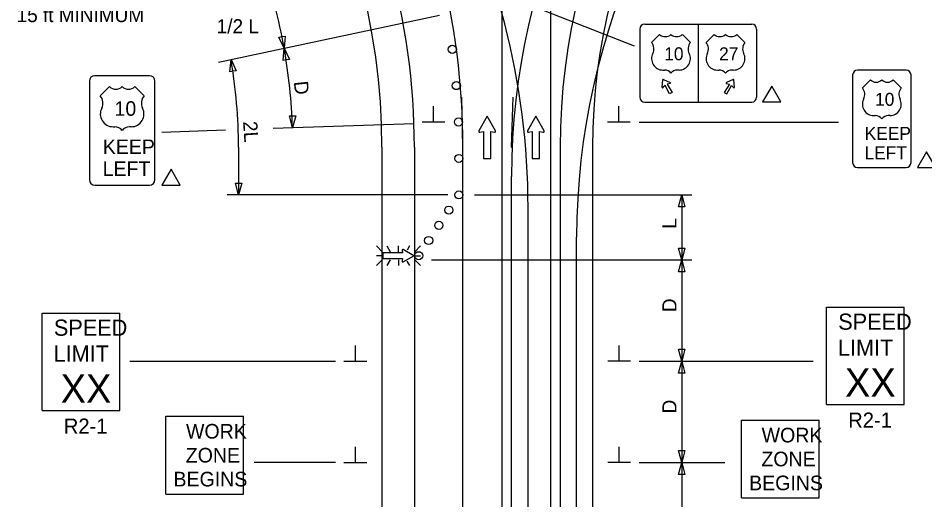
# Model space of a CAD drawing. Extents: x 16729 to 18500, y 5737 to 6974.
# Drawn here: x 16741.8 to 17189.6, y 6395.4 to 6633.2 of the extents above; entities that cross this region are included whole.
import ezdxf

# ---------------------------------------------------------------- set-up
doc = ezdxf.new("R2010")
doc.units = 0
for name, color, linetype in [('ALI_LEGAL_EX', 7, 'Continuous'), ('MT_SCRATCH_LEVEL_E', 7, 'Continuous'), ('PAVT_EDGE_EX', 7, 'Continuous'), ('TRAFFIC_SIGNS_PR', 7, 'Continuous'), ('TYPICAL_EX', 7, 'Continuous'), ('TYPICAL_TEXT_DIMEN_PR', 7, 'Continuous')]:
    doc.layers.add(name, color=color, linetype=linetype)

msp = doc.modelspace()

# ---------------------------------------------------------------- linework, layer by layer
at = {"layer": 'ALI_LEGAL_EX'}
for p, q in [((16980.68, 6974.12), (16980.68, 6155.98)), ((17004.68, 6974.12), (17004.68, 6155.98)), ((16980.68, 6891.53), (16980.68, 6027.61)), ((17004.68, 6891.53), (17004.68, 6027.61)), ((16961.51, 6069.17), (16961.51, 6569.52)), ((16985.51, 6054.68), (16985.51, 6555.03)), ((16993.65, 6039.29), (16993.65, 6539.64)), ((17017.65, 6024.8), (17017.65, 6525.15))]:
    msp.add_line(p, q, dxfattribs=at)
for points in [[(16961.46, 6569.17), (16961.51, 6569.52), (16960.94, 6594.16)], [(16985.56, 6569.17), (16985.51, 6569.52), (16986.34, 6594.15)], [(16961.51, 6469.17), (16961.51, 6494.17)], [(16985.51, 6469.17), (16985.51, 6494.17)]]:
    msp.add_lwpolyline(points, dxfattribs=at)
for centre, radius, start, end in [((16597.51, 6569.52), 364, 0, 57.2958), ((16629.65, 6539.64), 364, 0, 57.2958), ((17325.51, 6555.03), 340, 129.5666, 180), ((17357.65, 6525.15), 340, 129.5666, 180)]:
    msp.add_arc(centre, radius, start, end, dxfattribs=at)
at = {"layer": 'MT_SCRATCH_LEVEL_E'}
for p, q in [((16973.43, 6584.82), (16969.32, 6577.59)), ((16977.58, 6577.59), (16973.43, 6584.82)), ((16997.48, 6584.82), (16993.37, 6577.59)), ((17001.63, 6577.59), (16997.48, 6584.82)), ((16969.8, 6576.9), (16971.58, 6577.22)), ((16971.58, 6577.22), (16971.58, 6563.96)), ((16975.32, 6563.96), (16975.32, 6577.22)), ((16975.32, 6577.22), (16977.1, 6576.9)), ((16993.85, 6576.9), (16995.63, 6577.22)), ((16995.63, 6577.22), (16995.63, 6563.96)), ((16999.37, 6563.96), (16999.37, 6577.22)), ((16999.37, 6577.22), (17001.15, 6576.9)), ((16971.58, 6563.96), (16975.32, 6563.96)), ((16995.63, 6563.96), (16999.37, 6563.96))]:
    msp.add_line(p, q, dxfattribs=at)
for centre, start, end in [((16969.73, 6577.36), 150.4248, 279.9638), ((16977.17, 6577.36), 260.0362, 29.7731), ((16993.78, 6577.36), 150.4248, 279.9638), ((17001.22, 6577.36), 260.0362, 29.7731)]:
    msp.add_arc(centre, 0.463, start, end, dxfattribs=at)
at = {"layer": 'PAVT_EDGE_EX'}
for p, q in [((16921.51, 6569.52), (16921.51, 6043.9)), ((16937.51, 6569.52), (16937.51, 6043.9)), ((17009.51, 6569.52), (17009.51, 6043.9)), ((17025.51, 6569.52), (17025.51, 6043.9))]:
    msp.add_line(p, q, dxfattribs=at)
for centre, radius, start, end in [((16597.51, 6569.52), 340, 0, 62.1564), ((16597.51, 6569.52), 324, 0, 62.1564), ((17325.51, 6569.52), 316, 123.7854, 180), ((17325.51, 6569.52), 300, 123.7854, 180), ((17325.51, 6569.52), 300, 180, 180.00000277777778)]:
    msp.add_arc(centre, radius, start, end, dxfattribs=at)
at = {"layer": 'TRAFFIC_SIGNS_PR'}
for p, q in [((17048.86, 6627.84), (17048.86, 6594.19)), ((17051.26, 6630.24), (17104.13, 6630.24)), ((17077.7, 6630.24), (17077.7, 6591.79)), ((17106.53, 6627.84), (17106.53, 6594.19)), ((16806.71, 6604.81), (16779.71, 6604.81)), ((17153.94, 6605.16), (17153.94, 6561.91)), ((17180.37, 6607.57), (17156.34, 6607.57)), ((17182.77, 6561.91), (17182.77, 6605.16)), ((16777.01, 6602.11), (16777.01, 6553.51)), ((16809.41, 6553.51), (16809.41, 6602.11)), ((17059.85, 6599.15), (17060.14, 6602.78)), ((17060.51, 6602.99), (17063.79, 6601.42)), ((17094.88, 6602.99), (17091.6, 6601.42)), ((17095.54, 6599.15), (17095.25, 6602.78)), ((17051.26, 6591.79), (17104.13, 6591.79)), ((17156.34, 6559.51), (17180.37, 6559.51)), ((16779.71, 6550.81), (16806.71, 6550.81)), ((16921.58, 6517.92), (16918.76, 6520.74)), ((16923.88, 6520.74), (16925.51, 6517.92)), ((16929.67, 6517.92), (16929.67, 6520.74)), ((16935.13, 6520.74), (16933.93, 6518.65)), ((16940.57, 6520.74), (16937.75, 6517.92)), ((16921.58, 6515.89), (16918.76, 6515.89)), ((16937.75, 6515.89), (16940.57, 6515.89)), ((16921.58, 6513.86), (16918.76, 6511.04)), ((16925.53, 6513.86), (16923.9, 6511.04)), ((16929.67, 6513.86), (16929.67, 6511.04)), ((16933.85, 6513.23), (16935.11, 6511.04)), ((16940.57, 6511.04), (16937.75, 6513.86)), ((17141.06, 6490.51), (17179.46, 6490.51)), ((17141.06, 6442.51), (17141.06, 6490.51)), ((17179.46, 6442.51), (17179.46, 6490.51)), ((16753.73, 6487.55), (16792.13, 6487.55)), ((16753.73, 6439.55), (16753.73, 6487.55)), ((16792.13, 6439.55), (16792.13, 6487.55)), ((16753.73, 6439.55), (16792.13, 6439.55)), ((17141.06, 6442.51), (17179.46, 6442.51)), ((16814.75, 6398.28), (16814.75, 6436.68)), ((16814.75, 6436.68), (16853.15, 6436.68)), ((16853.15, 6398.28), (16853.15, 6436.68)), ((17099, 6396.4), (17099, 6434.8)), ((17099, 6434.8), (17137.4, 6434.8)), ((17137.4, 6396.4), (17137.4, 6434.8)), ((16814.75, 6398.28), (16853.15, 6398.28)), ((17099, 6396.4), (17137.4, 6396.4))]:
    msp.add_line(p, q, dxfattribs=at)
for points in [[(17063.75, 6600.94), (17062.34, 6600.55), (17064.86, 6596.56), (17063.53, 6595.8), (17061.33, 6599.97), (17060.29, 6598.94)], [(17091.64, 6600.94), (17093.05, 6600.55), (17090.53, 6596.56), (17091.86, 6595.8), (17094.06, 6599.97), (17095.1, 6598.94)], [(16931.49, 6518.57), (16931.72, 6517.28), (16922, 6517.28), (16922, 6514.53), (16931.72, 6514.53), (16931.49, 6513.23)], [(16931.99, 6512.88), (16937.3, 6515.89), (16931.99, 6518.93)]]:
    msp.add_lwpolyline(points, dxfattribs=at)
for centre in [(16956.26, 6617.81), (16958.22, 6599.92), (16959.28, 6581.96), (16959.5, 6563.96), (16959.5, 6545.96), (16959.5, 6545.96), (16954.53, 6538.45), (16949.56, 6530.94), (16944.59, 6523.44), (16939.62, 6515.93)]:
    msp.add_circle(centre, 2, dxfattribs=at)
for centre, radius, start, end in [((17051.26, 6627.84), 2.4, 90, 180), ((17051.26, 6627.84), 2.4, 90, 180), ((17104.13, 6627.84), 2.4, 0, 90), ((16779.71, 6602.1), 2.7, 90, 180), ((16806.71, 6602.1), 2.7, 0, 90), ((17156.34, 6605.16), 2.4, 90, 180), ((17180.37, 6605.16), 2.4, 0, 90), ((17060.4, 6602.76), 0.261, 64.4823, 175.5177), ((17063.68, 6601.19), 0.261, 285.9885, 64.4823), ((17091.71, 6601.19), 0.261, 115.5177, 254.0115), ((17094.99, 6602.76), 0.261, 4.4823, 115.5177), ((17060.11, 6599.13), 0.261, 175.5177, 314.0115), ((17095.28, 6599.13), 0.261, 225.9885, 4.4823), ((17051.26, 6594.19), 2.4, 180, 270), ((17104.13, 6594.19), 2.4, 270, 0), ((17156.34, 6561.91), 2.4, 180, 270), ((17180.37, 6561.91), 2.4, 270, 0), ((16779.71, 6553.5), 2.7, 180, 270), ((16806.71, 6553.5), 2.7, 270, 0), ((16931.83, 6518.63), 0.341, 61.4833, 189.9593), ((16931.83, 6513.18), 0.341, 170.7308, 298.8916)]:
    msp.add_arc(centre, radius, start, end, dxfattribs=at)
at = {"layer": 'TYPICAL_EX'}
for p, q in [((17054.62, 6621.23), (17058.62, 6625.23)), ((17073.84, 6621.23), (17069.84, 6625.23)), ((17081.55, 6621.23), (17085.55, 6625.23)), ((17100.77, 6621.23), (17096.77, 6625.23)), ((17060.22, 6607.6), (17061.02, 6607.6)), ((17068.24, 6607.6), (17067.44, 6607.6)), ((17087.15, 6607.6), (17087.95, 6607.6)), ((17095.17, 6607.6), (17094.37, 6607.6)), ((17158.74, 6598.76), (17162.75, 6602.76)), ((17177.97, 6598.76), (17173.96, 6602.76)), ((16782.41, 6594.91), (16786.91, 6599.41)), ((16804.01, 6594.91), (16799.51, 6599.41)), ((17164.34, 6585.13), (17165.14, 6585.13)), ((17172.36, 6585.13), (17171.56, 6585.13)), ((16788.7, 6579.59), (16789.6, 6579.59)), ((16797.71, 6579.59), (16796.81, 6579.59))]:
    msp.add_line(p, q, dxfattribs=at)
for centre, radius, start, end in [((17061.43, 6628.15), 4.05, 226.1404, 313.8596), ((17067.03, 6628.15), 4.05, 226.1404, 313.8596), ((17088.36, 6628.15), 4.05, 226.1404, 313.8596), ((17093.96, 6628.15), 4.05, 226.1404, 313.8596), ((17050.82, 6618.02), 4.97, 333.0977, 40.1936), ((17077.64, 6618.02), 4.97, 139.8064, 206.9023), ((17077.75, 6618.02), 4.97, 333.0977, 40.1936), ((17104.57, 6618.02), 4.97, 139.8064, 206.9023), ((17060.23, 6613.2), 5.6, 152.6698, 269.9013), ((17068.23, 6613.2), 5.6, 270.0987, 27.3302), ((17087.16, 6613.2), 5.6, 152.6698, 269.9013), ((17095.16, 6613.2), 5.6, 270.0987, 27.3302), ((17061.03, 6603.59), 4.01, 37.1038, 90.1385), ((17067.43, 6603.59), 4.01, 89.8615, 142.8962), ((17087.96, 6603.59), 4.01, 37.1038, 90.1385), ((17094.36, 6603.59), 4.01, 89.8615, 142.8962), ((17165.55, 6605.68), 4.05, 226.1404, 313.8596), ((17171.16, 6605.68), 4.05, 226.1404, 313.8596), ((16790.06, 6602.68), 4.55, 226.1404, 313.8596), ((16796.36, 6602.68), 4.55, 226.1404, 313.8596), ((17154.95, 6595.55), 4.97, 333.0977, 40.1936), ((17181.76, 6595.55), 4.97, 139.8064, 206.9023), ((16778.14, 6591.3), 5.58, 333.0977, 40.1936), ((16808.27, 6591.3), 5.58, 139.8064, 206.9023), ((17164.35, 6590.73), 5.6, 152.6698, 269.9013), ((17172.35, 6590.73), 5.6, 270.0987, 27.3302), ((16788.71, 6585.89), 6.29, 152.6698, 269.9013), ((16797.7, 6585.89), 6.29, 270.0987, 27.3302), ((17165.15, 6581.11), 4.01, 37.1038, 90.1385), ((17171.55, 6581.11), 4.01, 89.8615, 142.8962), ((16789.61, 6575.09), 4.51, 37.1038, 90.1385), ((16796.8, 6575.09), 4.51, 89.8615, 142.8962)]:
    msp.add_arc(centre, radius, start, end, dxfattribs=at)
at = {"layer": 'TYPICAL_TEXT_DIMEN_PR'}
for p, q in [((16964.45, 6651.69), (17046.11, 6619.48)), ((16840.84, 6611.45), (16949.94, 6634.73)), ((16870.65, 6623.86), (16872.19, 6624.13)), ((16873.22, 6618.36), (16870.65, 6623.86)), ((16872.19, 6624.13), (16873.74, 6624.4)), ((16873.74, 6624.4), (16873.22, 6618.36)), ((16872.69, 6612.31), (16873.22, 6618.36)), ((16873.22, 6618.36), (16875.79, 6612.86)), ((16846.44, 6606.71), (16846.97, 6612.76)), ((16846.97, 6612.76), (16849.54, 6607.26)), ((16874.24, 6612.59), (16872.69, 6612.31)), ((16875.79, 6612.86), (16874.24, 6612.59)), ((16847.99, 6606.98), (16846.44, 6606.71)), ((16849.54, 6607.26), (16847.99, 6606.98)), ((16946.99, 6581.91), (16946.99, 6589.7)), ((17038.53, 6581.91), (17038.53, 6589.7)), ((16877.34, 6579.16), (16875.77, 6585.02)), ((16875.77, 6585.02), (16877.34, 6585.02)), ((16877.34, 6585.02), (16878.91, 6585.02)), ((16878.91, 6585.02), (16877.34, 6579.16)), ((16812.87, 6576.94), (16844.31, 6578.02)), ((16867.78, 6578.83), (16937.31, 6581.22)), ((16952.61, 6581.91), (16941.36, 6581.91)), ((17044.15, 6581.91), (17032.9, 6581.91)), ((17048.51, 6581.91), (17146.98, 6581.91)), ((16850.69, 6569.52), (16850.69, 6545.96)), ((16850.69, 6545.96), (16849.12, 6551.82)), ((16849.12, 6551.82), (16850.69, 6551.82)), ((16850.69, 6551.82), (16852.26, 6551.82)), ((16852.26, 6551.82), (16850.69, 6545.96)), ((16954.01, 6545.96), (16845.14, 6545.96)), ((16967.28, 6545.96), (17074.51, 6545.96)), ((17067.94, 6540.1), (17069.51, 6545.96)), ((17069.51, 6545.96), (17069.51, 6513.85)), ((17069.51, 6545.96), (17071.08, 6540.1)), ((17069.51, 6540.1), (17067.94, 6540.1)), ((17071.08, 6540.1), (17069.51, 6540.1)), ((17069.51, 6513.85), (17067.94, 6519.72)), ((17067.94, 6519.72), (17069.51, 6519.72)), ((17069.51, 6519.72), (17071.08, 6519.72)), ((17071.08, 6519.72), (17069.51, 6513.85)), ((16945.91, 6513.85), (17074.51, 6513.85)), ((17067.94, 6507.99), (17069.51, 6513.85)), ((17069.51, 6513.85), (17069.51, 6463.85)), ((17069.51, 6513.85), (17071.08, 6507.99)), ((17069.51, 6507.99), (17067.94, 6507.99)), ((17071.08, 6507.99), (17069.51, 6507.99)), ((16908.39, 6463.85), (16908.39, 6471.64)), ((17038.64, 6463.85), (17038.64, 6471.64)), ((17069.51, 6463.85), (17067.94, 6469.72)), ((17067.94, 6469.72), (17069.51, 6469.72)), ((17069.51, 6469.72), (17071.08, 6469.72)), ((17071.08, 6469.72), (17069.51, 6463.85)), ((16796.96, 6463.85), (16898.51, 6463.85)), ((16902.76, 6463.85), (16914.01, 6463.85)), ((17044.26, 6463.85), (17033.01, 6463.85)), ((17048.51, 6463.85), (17134.47, 6463.85)), ((17067.94, 6457.99), (17069.51, 6463.85)), ((17069.51, 6463.85), (17069.51, 6413.85)), ((17069.51, 6463.85), (17071.08, 6457.99)), ((17069.51, 6457.99), (17067.94, 6457.99)), ((17071.08, 6457.99), (17069.51, 6457.99)), ((16908.39, 6413.85), (16908.39, 6421.64)), ((17038.64, 6413.85), (17038.64, 6421.64)), ((17069.51, 6413.85), (17067.94, 6419.72)), ((17067.94, 6419.72), (17069.51, 6419.72)), ((17069.51, 6419.72), (17071.08, 6419.72)), ((17071.08, 6419.72), (17069.51, 6413.85)), ((16898.51, 6413.85), (16858.48, 6413.85)), ((16902.76, 6413.85), (16914.01, 6413.85)), ((17044.26, 6413.85), (17033.01, 6413.85)), ((17048.51, 6413.85), (17090.83, 6413.85)), ((17067.94, 6407.99), (17069.51, 6413.85)), ((17069.51, 6413.85), (17069.51, 6363.85)), ((17069.51, 6413.85), (17071.08, 6407.99)), ((17069.51, 6407.99), (17067.94, 6407.99)), ((17071.08, 6407.99), (17069.51, 6407.99))]:
    msp.add_line(p, q, dxfattribs=at)
for points in [[(17114.01, 6599.66), (17109.48, 6591.83), (17118.53, 6591.83)], [(17190.44, 6567.27), (17185.92, 6559.44), (17194.97, 6559.44)], [(16817.37, 6558.64), (16812.84, 6550.81), (16821.89, 6550.81)]]:
    msp.add_lwpolyline(points, close=True, dxfattribs=at)
for radius, start, end in [(280, 10.0461, 14.4629), (280, 1.9734, 10.046), (253.18, 0, 9.834)]:
    msp.add_arc((16597.51, 6569.52), radius, start, end, dxfattribs=at)

# ---------------------------------------------------------------- texts
at = {"layer": 'TRAFFIC_SIGNS_PR'}
for s, height, p in [('10', 6.408, (17060.89, 6612.42)), ('27', 6.408, (17087.99, 6612.42)), ('10', 6.408, (17165.01, 6589.94)), ('10', 7.2, (16789.45, 6585.01)), ('KEEP', 6.408, (17159.88, 6573.12)), ('KEEP', 7.2, (16783.69, 6566.11)), ('LEFT', 6.408, (17159.79, 6563.51)), ('LEFT', 7.2, (16783.59, 6555.31)), ('SPEED', 8, (16759.5, 6476.41)), ('SPEED', 8, (17146.83, 6479.37)), ('LIMIT', 8, (17146.67, 6466.57)), ('LIMIT', 8, (16759.34, 6463.61)), ('XX', 14.031, (16762.85, 6443.31)), ('XX', 14.031, (17150.18, 6446.27)), ('R2-1', 7.44, (16764.41, 6428.11)), ('R2-1', 7.44, (17151.74, 6431.07)), ('WORK', 7.217, (16824.75, 6425.65)), ('WORK', 7.217, (17109, 6423.77)), ('ZONE', 7.217, (16824.63, 6413.84)), ('ZONE', 7.217, (17108.88, 6411.96)), ('BEGINS', 7.217, (16818.56, 6402.03)), ('BEGINS', 7.217, (17102.81, 6400.15))]:
    msp.add_text(s, height=height, dxfattribs=at).set_placement(p)
at = {"layer": 'TYPICAL_TEXT_DIMEN_PR'}
for s, p in [('15 ft MINIMUM', (16741.13, 6631.27)), ('1/2 L', (16839.91, 6625.71))]:
    msp.add_text(s, height=7, dxfattribs=at).set_placement(p)
for s, rotation, p in [('D', 276.0098, (16877.95, 6601.84)), ('2L', 273.8016, (16852.9, 6582.16)), ('L', 90, (17066.95, 6529.26)), ('D', 90, (17066.95, 6488.07)), ('D', 90, (17066.95, 6438.07))]:
    msp.add_text(s, height=7, rotation=rotation, dxfattribs=at).set_placement(p)

doc.saveas('drawing.dxf')
